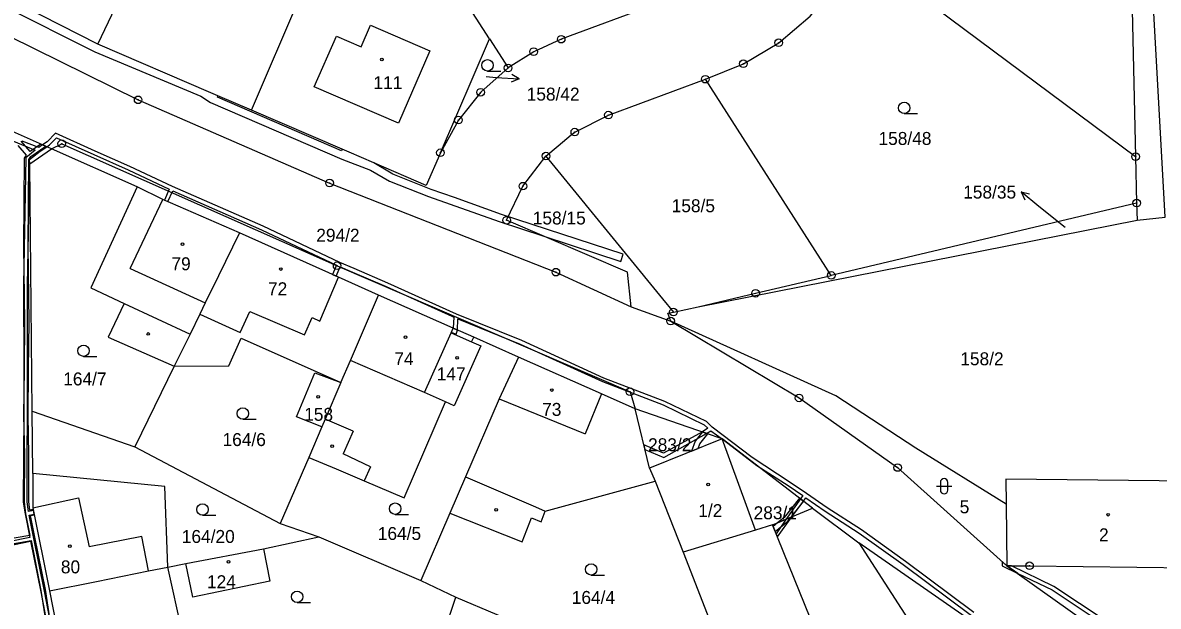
# Model space of a CAD drawing. Extents: x -779723 to -777378, y -1011169 to -1009297.
# Drawn here: x -779372 to -779222.9, y -1010201 to -1010124.4 of the extents above; entities that cross this region are included whole.
import ezdxf

# ---------------------------------------------------------------- set-up
doc = ezdxf.new("R2010")
doc.units = 0
for name, color, linetype in [('Hranice parcel', 7, 'Continuous'), ('Parcelní čísla', 7, 'Continuous'), ('Pop  PČ popisy', 7, 'Continuous'), ('Vnitřní kresba', 7, 'Continuous'), ('Věcná břemena k části', 7, 'Continuous'), ('Značky bodu BP', 7, 'Continuous'), ('Značky budov', 7, 'Continuous'), ('Značky kultur', 7, 'Continuous')]:
    doc.layers.add(name, color=color, linetype=linetype)

msp = doc.modelspace()

# ---------------------------------------------------------------- linework, layer by layer
at = {"layer": 'Hranice parcel'}
for p, q in [((-779342.01, -1010135.87), (-779327.06, -1010101.1)), ((-779310.76, -1010126.49), (-779327.06, -1010101.1)), ((-779262.32, -1010114.82), (-779225.9, -1010141.96)), ((-779317.19, -1010141.44), (-779310.76, -1010126.49)), ((-779310.76, -1010126.49), (-779308.3, -1010130.32)), ((-779265.87, -1010157.54), (-779282.4, -1010131.79)), ((-779368.25, -1010140.93), (-779379.75, -1010135.84)), ((-779356.99, -1010145.94), (-779368.25, -1010140.93)), ((-779306.36, -1010145.83), (-779303.34, -1010141.89)), ((-779225.9, -1010141.96), (-779225.76, -1010148.05)), ((-779225.76, -1010148.05), (-779265.87, -1010157.54)), ((-779225.76, -1010148.05), (-779225.71, -1010150.28)), ((-779283.36, -1010161.68), (-779225.71, -1010150.28)), ((-779225.71, -1010150.28), (-779222.02, -1010149.91)), ((-779292.12, -1010161.67), (-779286.95, -1010163.54)), ((-779286.59, -1010162.36), (-779283.36, -1010161.68)), ((-779319.28, -1010172.9), (-779315.79, -1010165.07)), ((-779315.79, -1010165.07), (-779313.09, -1010166.28)), ((-779313.09, -1010166.28), (-779312.82, -1010165.66)), ((-779306.92, -1010168.28), (-779312.82, -1010165.66)), ((-779311.89, -1010166.81), (-779315.38, -1010174.67)), ((-779313.09, -1010166.28), (-779311.89, -1010166.81)), ((-779352.15, -1010169.47), (-779357.33, -1010180.05)), ((-779336.07, -1010176.09), (-779333.7, -1010170.34)), ((-779333.7, -1010170.34), (-779330.25, -1010171.61)), ((-779316.5, -1010174.16), (-779319.28, -1010172.9)), ((-779315.38, -1010174.67), (-779316.5, -1010174.16)), ((-779370.73, -1010183.55), (-779370.81, -1010175.38)), ((-779370.81, -1010175.38), (-779357.33, -1010180.05)), ((-779332.74, -1010177.43), (-779336.07, -1010176.09)), ((-779289.74, -1010182.83), (-779291.6, -1010175.07)), ((-779332.74, -1010177.43), (-779334.46, -1010181.43)), ((-779280.19, -1010178.98), (-779289.74, -1010182.83)), ((-779268.33, -1010188.11), (-779280.19, -1010178.98)), ((-779275.82, -1010190.98), (-779280.19, -1010178.98)), ((-779357.33, -1010180.05), (-779338.22, -1010190.12)), ((-779334.46, -1010181.43), (-779338.22, -1010190.12)), ((-779289.74, -1010182.83), (-779288.98, -1010184.55)), ((-779288.98, -1010184.55), (-779285.33, -1010193.87)), ((-779242.9, -1010187.56), (-779242.79, -1010195.65)), ((-779315.95, -1010188.73), (-779319.77, -1010197.59)), ((-779273.57, -1010190.29), (-779268.33, -1010188.11)), ((-779268.33, -1010188.11), (-779262.24, -1010192.63)), ((-779338.22, -1010190.12), (-779333.16, -1010191.86)), ((-779275.82, -1010190.98), (-779285.33, -1010193.87)), ((-779273.57, -1010190.29), (-779275.82, -1010190.98)), ((-779261.29, -1010220.59), (-779273.57, -1010190.29)), ((-779340.44, -1010193.45), (-779333.16, -1010191.86)), ((-779333.16, -1010191.86), (-779319.77, -1010197.59)), ((-779350.63, -1010195.35), (-779340.44, -1010193.45)), ((-779340.44, -1010193.45), (-779339.6, -1010197.69)), ((-779285.33, -1010193.87), (-779276.66, -1010216.01)), ((-779246.71, -1010203.46), (-779262.24, -1010192.63)), ((-779352.97, -1010195.83), (-779350.63, -1010195.35)), ((-779349.69, -1010199.77), (-779350.63, -1010195.35)), ((-779349.54, -1010211.54), (-779352.97, -1010195.83)), ((-779339.6, -1010197.69), (-779349.69, -1010199.77)), ((-779319.77, -1010197.59), (-779315.16, -1010199.77)), ((-779317, -1010205.16), (-779315.16, -1010199.77)), ((-779315.16, -1010199.77), (-779282.2, -1010213.67))]:
    msp.add_line(p, q, dxfattribs=at)
for points in [[(-779222.02, -1010149.91), (-779224.22, -1010110.43), (-779227.75, -1010085.02), (-779232.26, -1010057.56), (-779233.9, -1010041.71)], [(-779342.01, -1010135.87), (-779346.4, -1010133.98), (-779347.32, -1010133.59), (-779362.17, -1010127.2), (-779340.06, -1010080.85)], [(-779443.22, -1010085.81), (-779433.43, -1010091.77), (-779409.97, -1010106.05), (-779380.8, -1010122.72), (-779356.88, -1010134.5), (-779331.75, -1010145.42), (-779302.03, -1010157.12), (-779292.12, -1010161.67)], [(-779228.25, -1010097.65), (-779226.51, -1010114.99), (-779225.9, -1010141.96)], [(-779282.4, -1010131.79), (-779277.41, -1010129.77), (-779272.77, -1010127.01), (-779268.62, -1010123.54), (-779265.13, -1010119.44), (-779262.32, -1010114.82)], [(-779288.77, -1010121.88), (-779301.33, -1010126.54), (-779304.94, -1010128.18), (-779308.3, -1010130.32)], [(-779330.83, -1010126.13), (-779327.61, -1010127.53), (-779326.36, -1010124.72), (-779318.57, -1010128.06), (-779322.68, -1010137.57), (-779333.75, -1010132.81), (-779330.83, -1010126.13)], [(-779308.3, -1010130.32), (-779311.9, -1010133.51), (-779314.82, -1010137.15), (-779317.19, -1010141.44)], [(-779299.54, -1010138.73), (-779295.13, -1010136.5), (-779282.4, -1010131.79)], [(-779317.19, -1010141.44), (-779319.05, -1010145.75), (-779325.94, -1010142.79), (-779329.19, -1010141.39), (-779330.11, -1010140.99), (-779342.01, -1010135.87)], [(-779303.34, -1010141.89), (-779301.73, -1010140.55), (-779300, -1010139.11), (-779299.54, -1010138.73)], [(-779370.81, -1010175.38), (-779371.12, -1010142.88), (-779368.25, -1010140.93)], [(-779303.34, -1010141.89), (-779292.91, -1010154.64), (-779288.01, -1010160.63), (-779286.59, -1010162.36)], [(-779356.99, -1010145.94), (-779363.09, -1010159.19), (-779358.72, -1010161.22), (-779360.82, -1010165.67), (-779352.15, -1010169.47)], [(-779343.57, -1010151.97), (-779353.64, -1010147.57), (-779356.99, -1010145.94)], [(-779292.12, -1010161.67), (-779292.63, -1010157.12), (-779308.49, -1010150.3), (-779306.36, -1010145.83)], [(-779343.57, -1010151.97), (-779346.34, -1010157.62), (-779348.07, -1010161.15), (-779348.79, -1010162.63), (-779350.07, -1010165.25), (-779350.37, -1010165.85), (-779350.86, -1010166.85), (-779352.15, -1010169.47)], [(-779325.31, -1010160.13), (-779330.56, -1010157.78), (-779343.57, -1010151.97)], [(-779283.36, -1010161.68), (-779275.8, -1010159.89), (-779265.87, -1010157.54)], [(-779330.25, -1010171.61), (-779329.01, -1010168.72), (-779325.31, -1010160.13)], [(-779312.82, -1010165.66), (-779315.53, -1010164.48), (-779325.31, -1010160.13)], [(-779286.95, -1010163.54), (-779287.32, -1010162.52), (-779286.59, -1010162.36)], [(-779286.95, -1010163.54), (-779270.09, -1010173.63), (-779257.16, -1010182.76), (-779242.79, -1010195.65)], [(-779242.9, -1010187.56), (-779254.75, -1010180.24), (-779265.26, -1010173.35), (-779286.95, -1010163.54)], [(-779352.15, -1010169.47), (-779344.96, -1010169.41), (-779343.34, -1010165.79), (-779330.25, -1010171.61)], [(-779306.92, -1010168.28), (-779309.48, -1010173.73), (-779313.9, -1010183.97), (-779315.95, -1010188.73)], [(-779291.6, -1010175.07), (-779296.03, -1010173.11), (-779306.92, -1010168.28)], [(-779330.25, -1010171.61), (-779332.31, -1010176.42), (-779332.74, -1010177.43)], [(-779334.46, -1010181.43), (-779330.86, -1010182.95), (-779327.18, -1010184.51), (-779321.95, -1010186.72), (-779316.5, -1010174.16)], [(-779280.19, -1010178.98), (-779282.25, -1010178.28), (-779291.6, -1010175.07)], [(-779370.73, -1010183.55), (-779370.69, -1010188.04), (-779368.51, -1010198.95)], [(-779352.97, -1010195.83), (-779353.39, -1010185.24), (-779370.73, -1010183.55)], [(-779315.95, -1010188.73), (-779306.46, -1010192.53), (-779305.24, -1010189.37), (-779303.95, -1010189.91), (-779303.42, -1010188.49), (-779288.98, -1010184.55)], [(-779218.76, -1010184.53), (-779242.94, -1010184.31), (-779242.9, -1010187.56)], [(-779262.24, -1010192.63), (-779254.52, -1010204.61), (-779251.62, -1010216.72)], [(-779368.51, -1010198.95), (-779362.33, -1010197.71), (-779355.52, -1010196.34), (-779352.97, -1010195.83)], [(-779242.79, -1010195.65), (-779223.48, -1010209.38), (-779213.39, -1010216.37), (-779205.69, -1010223.63)], [(-779242.79, -1010195.65), (-779239.83, -1010195.66), (-779218.67, -1010195.92)], [(-779368.51, -1010198.95), (-779367.68, -1010203.17), (-779367.63, -1010203.52), (-779367.55, -1010203.87), (-779365.42, -1010214.66)]]:
    msp.add_lwpolyline(points, dxfattribs=at)
at = {"layer": 'Pop  PČ popisy'}
for p, q in [((-779306.86, -1010131.76), (-779307.82, -1010131.19)), ((-779311.2, -1010131.45), (-779309.85, -1010131.55)), ((-779309.85, -1010131.55), (-779306.86, -1010131.76)), ((-779306.86, -1010131.76), (-779307.89, -1010132.19)), ((-779238.59, -1010148.48), (-779240.92, -1010146.59)), ((-779240.92, -1010146.59), (-779239.83, -1010146.83)), ((-779240.92, -1010146.59), (-779240.46, -1010147.61)), ((-779235.13, -1010151.25), (-779238.59, -1010148.48))]:
    msp.add_line(p, q, dxfattribs=at)
at = {"layer": 'Vnitřní kresba'}
for p, q in [((-779368.25, -1010140.93), (-779366.91, -1010140.27)), ((-779366.91, -1010140.27), (-779330.75, -1010156.28)), ((-779357.95, -1010156.63), (-779353.64, -1010147.57)), ((-779357.95, -1010156.63), (-779348.07, -1010161.15)), ((-779330.75, -1010156.28), (-779292.29, -1010172.82)), ((-779333.01, -1010163.53), (-779330.56, -1010157.78)), ((-779358.72, -1010161.22), (-779350.07, -1010165.25)), ((-779334.03, -1010163.08), (-779333.01, -1010163.53)), ((-779315.79, -1010165.07), (-779315.53, -1010164.48)), ((-779319.28, -1010172.9), (-779329.01, -1010168.72)), ((-779296.03, -1010173.11), (-779298.16, -1010178.34)), ((-779292.29, -1010172.82), (-779291.6, -1010175.07)), ((-779309.48, -1010173.73), (-779298.16, -1010178.34)), ((-779328.64, -1010178), (-779332.31, -1010176.42)), ((-779328.64, -1010178), (-779329.98, -1010180.98)), ((-779326.39, -1010182.67), (-779329.98, -1010180.98)), ((-779326.39, -1010182.67), (-779327.18, -1010184.51)), ((-779313.9, -1010183.97), (-779304.69, -1010187.94)), ((-779370.69, -1010188.04), (-779364.7, -1010186.76)), ((-779364.7, -1010186.76), (-779363.31, -1010193.19)), ((-779304.69, -1010187.94), (-779303.42, -1010188.49)), ((-779356.41, -1010191.83), (-779363.31, -1010193.19)), ((-779355.52, -1010196.34), (-779356.41, -1010191.83))]:
    msp.add_line(p, q, dxfattribs=at)
msp.add_lwpolyline([(-779348.79, -1010162.63), (-779343.48, -1010165.02), (-779342.22, -1010162.27), (-779335.04, -1010165.34), (-779334.03, -1010163.08)], dxfattribs=at)
at = {"layer": 'Věcná břemena k části'}
for points in [[(-779374.62, -1010122.18), (-779362.56, -1010128.21), (-779348.65, -1010134.02), (-779347.39, -1010134.85), (-779330.12, -1010142.3), (-779326.38, -1010143.73), (-779323.87, -1010145.16), (-779318.76, -1010147.2), (-779309.49, -1010150.47), (-779303.59, -1010152.4), (-779293.48, -1010155.71), (-779293.17, -1010154.76), (-779309.17, -1010149.53), (-779315.36, -1010147.34), (-779318.4, -1010146.26), (-779323.43, -1010144.26), (-779325.94, -1010142.79), (-779329.19, -1010141.39), (-779330.11, -1010140.99), (-779330.19, -1010141.18), (-779346.48, -1010134.15), (-779346.4, -1010133.98), (-779347.32, -1010133.59), (-779362.17, -1010127.2), (-779371.98, -1010122.22)], [(-779379, -1010137.58), (-779370.39, -1010141.1), (-779371.64, -1010142.11), (-779371.92, -1010158.77), (-779371.9, -1010169.83), (-779371.91, -1010175.84), (-779371.94, -1010181.3), (-779371.97, -1010187.3), (-779371.73, -1010188.85), (-779371.11, -1010191.94), (-779379.79, -1010193.7)], [(-779368.33, -1010203.39), (-779369.04, -1010198.78), (-779370.43, -1010191.91), (-779371.01, -1010189.05), (-779370.51, -1010188.95), (-779370.65, -1010188.26), (-779371.12, -1010188.36), (-779371.25, -1010187.24), (-779371.22, -1010181.1), (-779371.34, -1010175.92), (-779371.27, -1010169.85), (-779371.21, -1010163.62), (-779371.33, -1010153.7), (-779371.23, -1010142.33), (-779370.96, -1010141.92), (-779368.99, -1010140.6), (-779369.64, -1010140.32), (-779371.08, -1010141.28), (-779372.26, -1010139.91)], [(-779368.3, -1010203.56), (-779369.17, -1010198.98), (-779370.57, -1010192.09), (-779371.19, -1010189.01), (-779370.52, -1010188.89), (-779370.62, -1010188.4), (-779371.28, -1010188.52), (-779371.47, -1010187.26), (-779371.44, -1010181.3), (-779371.41, -1010175.84), (-779371.4, -1010169.83), (-779371.42, -1010158.77), (-779371.12, -1010142.88), (-779371.14, -1010142.35), (-779369.76, -1010141.23), (-779368.88, -1010140.65), (-779369.42, -1010140.41), (-779369.93, -1010140.74), (-779372.11, -1010139.91)], [(-779247.14, -1010201.81), (-779256.12, -1010195.09), (-779261.91, -1010190.95), (-779266.38, -1010188.06), (-779269.11, -1010186.17), (-779271.25, -1010184.72), (-779276.23, -1010181.44), (-779281.51, -1010177.47), (-779282.25, -1010176.73), (-779287.73, -1010174.08), (-779295.72, -1010171.02), (-779306.51, -1010166.11), (-779315.09, -1010162.63), (-779324.11, -1010158.57), (-779328.53, -1010156.65), (-779330.39, -1010155.87), (-779340.47, -1010151.1), (-779352.36, -1010145.89), (-779357.99, -1010143.24), (-779362.51, -1010141.24), (-779367.72, -1010138.89), (-779368.83, -1010140.03), (-779369.42, -1010140.41), (-779368.88, -1010140.65), (-779368.51, -1010140.41), (-779367.6, -1010139.49), (-779362.71, -1010141.69), (-779358.19, -1010143.7), (-779352.79, -1010146.24), (-779353.43, -1010147.66), (-779352.97, -1010147.86), (-779352.33, -1010146.45), (-779340.67, -1010151.55), (-779330.82, -1010156.22), (-779331.36, -1010157.42), (-779330.86, -1010157.65), (-779330.36, -1010156.42), (-779328.73, -1010157.11), (-779324.31, -1010159.02), (-779315.7, -1010162.9), (-779315.44, -1010163.02), (-779315.53, -1010164.48), (-779314.95, -1010164.73), (-779314.92, -1010163.26), (-779306.7, -1010166.56), (-779295.91, -1010171.48), (-779287.92, -1010174.53), (-779282.55, -1010177.15), (-779282.08, -1010177.61), (-779282.79, -1010178.09), (-779282.25, -1010178.28), (-779281.69, -1010177.96), (-779280.19, -1010178.98), (-779275.63, -1010182.49), (-779271.53, -1010185.14), (-779269.6, -1010186.44), (-779269.92, -1010186.89), (-779269.53, -1010187.19), (-779269.19, -1010186.73), (-779266.66, -1010188.48), (-779262.19, -1010191.37), (-779256.41, -1010195.49), (-779247.46, -1010202.19)], [(-779372.68, -1010140.49), (-779371.58, -1010141.77), (-779371.83, -1010142.15), (-779371.93, -1010153.7), (-779371.81, -1010163.62), (-779371.87, -1010169.85), (-779371.94, -1010175.92), (-779371.82, -1010181.1), (-779371.85, -1010187.28), (-779371.67, -1010188.82), (-779371.09, -1010191.68), (-779378.6, -1010192.95)], [(-779379.69, -1010194.2), (-779371.02, -1010192.43), (-779369.66, -1010199.07), (-779368.73, -1010203.94)], [(-779378.46, -1010193.63), (-779370.95, -1010192.36), (-779369.64, -1010198.88), (-779368.86, -1010203.88)]]:
    msp.add_lwpolyline(points, dxfattribs=at)
for points in [[(-779315.53, -1010164.48), (-779315.76, -1010165), (-779315.14, -1010165.27), (-779314.95, -1010164.73)], [(-779282.25, -1010178.28), (-779282.79, -1010178.09), (-779287.88, -1010180.89), (-779290.47, -1010179.77), (-779290.33, -1010180.38), (-779287.86, -1010181.45)], [(-779282.09, -1010178.33), (-779282.79, -1010178.09), (-779283.75, -1010179.3), (-779284.22, -1010180.61), (-779283.35, -1010180.25), (-779283.13, -1010179.64)], [(-779269.49, -1010187.21), (-779270.05, -1010186.78), (-779272.06, -1010189.3), (-779272.93, -1010190.02), (-779271.15, -1010189.28)], [(-779269.53, -1010187.19), (-779269.92, -1010186.89), (-779271.85, -1010189.57), (-779271.02, -1010189.23)], [(-779273.21, -1010191.17), (-779271.56, -1010189.8), (-779271.15, -1010189.28), (-779272.93, -1010190.02), (-779273.49, -1010190.49)], [(-779271.85, -1010189.57), (-779273.1, -1010191.46), (-779272.94, -1010191.86), (-779271.02, -1010189.23)], [(-779241.36, -1010196.66), (-779242.79, -1010195.65), (-779243.41, -1010195.09), (-779243.42, -1010195.68)], [(-779220.81, -1010211.23), (-779218.5, -1010212.83), (-779226.54, -1010205.05), (-779236.62, -1010198.39), (-779242.2, -1010195.65), (-779242.79, -1010195.65), (-779241.36, -1010196.66), (-779236.86, -1010198.82), (-779226.86, -1010205.45)]]:
    msp.add_lwpolyline(points, close=True, dxfattribs=at)
at = {"layer": 'Značky bodu BP'}
for centre, radius in [((-779301.33, -1010126.54), 0.5), ((-779301.33, -1010126.54), 0.0303), ((-779272.77, -1010127.01), 0.5), ((-779304.94, -1010128.18), 0.5), ((-779304.94, -1010128.18), 0.0303), ((-779272.77, -1010127.01), 0.0303), ((-779308.3, -1010130.32), 0.5), ((-779277.41, -1010129.77), 0.5), ((-779277.41, -1010129.77), 0.0303), ((-779308.3, -1010130.32), 0.0303), ((-779282.4, -1010131.79), 0.5), ((-779282.4, -1010131.79), 0.0303), ((-779356.88, -1010134.5), 0.5), ((-779311.9, -1010133.51), 0.5), ((-779311.9, -1010133.51), 0.0303), ((-779356.88, -1010134.5), 0.0303), ((-779314.82, -1010137.15), 0.5), ((-779314.82, -1010137.15), 0.0303), ((-779295.13, -1010136.5), 0.5), ((-779295.13, -1010136.5), 0.0303), ((-779299.54, -1010138.73), 0.5), ((-779299.54, -1010138.73), 0.0303), ((-779366.91, -1010140.27), 0.5), ((-779366.91, -1010140.27), 0.0303), ((-779317.19, -1010141.44), 0.5), ((-779317.19, -1010141.44), 0.0303), ((-779303.34, -1010141.89), 0.5), ((-779303.34, -1010141.89), 0.0303), ((-779225.9, -1010141.96), 0.5), ((-779225.9, -1010141.96), 0.0303), ((-779331.75, -1010145.42), 0.5), ((-779331.75, -1010145.42), 0.0303), ((-779306.36, -1010145.83), 0.5), ((-779306.36, -1010145.83), 0.0303), ((-779225.76, -1010148.05), 0.5), ((-779225.76, -1010148.05), 0.0303), ((-779308.49, -1010150.3), 0.5), ((-779308.49, -1010150.3), 0.0303), ((-779330.75, -1010156.28), 0.5), ((-779330.75, -1010156.28), 0.0303), ((-779302.03, -1010157.12), 0.5), ((-779302.03, -1010157.12), 0.0303), ((-779265.87, -1010157.54), 0.5), ((-779265.87, -1010157.54), 0.0303), ((-779275.8, -1010159.89), 0.5), ((-779275.8, -1010159.89), 0.0303), ((-779286.59, -1010162.36), 0.5), ((-779286.59, -1010162.36), 0.0303), ((-779286.95, -1010163.54), 0.5), ((-779286.95, -1010163.54), 0.0303), ((-779292.29, -1010172.82), 0.5), ((-779292.29, -1010172.82), 0.0303), ((-779270.09, -1010173.63), 0.5), ((-779270.09, -1010173.63), 0.0303), ((-779257.16, -1010182.76), 0.5), ((-779257.16, -1010182.76), 0.0303), ((-779239.83, -1010195.66), 0.5), ((-779239.83, -1010195.66), 0.0303)]:
    msp.add_circle(centre, radius, dxfattribs=at)
at = {"layer": 'Značky budov'}
for centre in [(-779324.86, -1010129.2), (-779351.07, -1010153.44), (-779338.14, -1010156.71), (-779355.55, -1010165.23), (-779321.78, -1010165.65), (-779315.01, -1010168.37), (-779302.57, -1010172.59), (-779333.25, -1010173.47), (-779331.39, -1010179.95), (-779282.02, -1010184.99), (-779309.87, -1010188.31), (-779229.52, -1010188.95), (-779365.84, -1010193.09), (-779345.03, -1010195.14)]:
    msp.add_circle(centre, 0.175, dxfattribs=at)
at = {"layer": 'Značky kultur'}
for p, q in [((-779311, -1010130.72), (-779309.25, -1010130.72)), ((-779256.28, -1010136.31), (-779254.53, -1010136.31)), ((-779364.05, -1010168.18), (-779362.3, -1010168.18)), ((-779343.13, -1010176.42), (-779341.38, -1010176.42)), ((-779251.54, -1010184.72), (-779251.54, -1010185.72)), ((-779250.54, -1010185.72), (-779250.54, -1010184.72)), ((-779252.04, -1010185.22), (-779250.04, -1010185.22)), ((-779348.43, -1010189.02), (-779346.68, -1010189.02)), ((-779323.13, -1010188.91), (-779321.38, -1010188.91)), ((-779297.39, -1010196.88), (-779295.64, -1010196.88)), ((-779336.01, -1010200.47), (-779334.26, -1010200.47))]:
    msp.add_line(p, q, dxfattribs=at)
for centre in [(-779311, -1010129.97), (-779256.28, -1010135.56), (-779364.05, -1010167.43), (-779343.13, -1010175.67), (-779348.43, -1010188.27), (-779323.13, -1010188.16), (-779297.39, -1010196.13), (-779336.01, -1010199.72)]:
    msp.add_circle(centre, 0.75, dxfattribs=at)
for centre, start, end in [((-779251.04, -1010184.72), 0, 180), ((-779251.04, -1010185.72), 180, 359.9879)]:
    msp.add_arc(centre, 0.5, start, end, dxfattribs=at)

# ---------------------------------------------------------------- texts
at = {"layer": 'Parcelní čísla'}
for s, p in [('111', (-779325.98, -1010133.1)), ('158/42', (-779305.86, -1010134.6)), ('158/48', (-779259.66, -1010140.42)), ('158/35', (-779248.54, -1010147.46)), ('158/5', (-779286.82, -1010149.25)), ('158/15', (-779305.06, -1010150.86)), ('294/2', (-779333.49, -1010153.12)), ('79', (-779352.51, -1010156.87)), ('72', (-779339.83, -1010160.15)), ('74', (-779323.23, -1010169.32)), ('158/2', (-779248.92, -1010169.34)), ('164/7', (-779366.72, -1010171.98)), ('147', (-779317.67, -1010171.32)), ('73', (-779303.83, -1010175.98)), ('158', (-779335.08, -1010176.63)), ('164/6', (-779345.8, -1010179.94)), ('283/2', (-779289.92, -1010180.62)), ('1/2', (-779283.33, -1010189.27)), ('283/1', (-779276.06, -1010189.55)), ('5', (-779249, -1010188.77)), ('164/20', (-779351.15, -1010192.66)), ('164/5', (-779325.41, -1010192.27)), ('2', (-779230.7, -1010192.44)), ('80', (-779367.03, -1010196.65)), ('124', (-779347.84, -1010198.6)), ('164/4', (-779299.94, -1010200.66))]:
    msp.add_text(s, height=1.7, dxfattribs=at).set_placement(p)

doc.saveas('drawing.dxf')
